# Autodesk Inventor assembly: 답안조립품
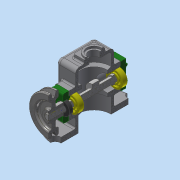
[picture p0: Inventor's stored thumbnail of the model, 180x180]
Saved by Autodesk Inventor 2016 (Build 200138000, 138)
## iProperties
Created: 2018-07
Part Number: 답안조립품
Material: 일반
Document SubType Name: Assembly
Designer: 2-PC02
Author: 2-PC02
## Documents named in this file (9)
- C:\Users\2-PC02\Desktop\480708V1008\480708V1008\답안조립품.iam
- C:\Users\2-PC02\Desktop\480708V1008\480708V1008\본체.ipt
- C:\Users\2-PC02\Desktop\480708V1008\뒤커버.ipt
- C:\Users\2-PC02\Desktop\480708V1008\편심축.ipt
- C:\Users\2-PC02\Desktop\480708V1008\베어링 12x32x10.ipt
- C:\Users\2-PC02\Desktop\480708V1008\앞커버.ipt
- C:\Users\2-PC02\Desktop\480708V1008\오일 실 12 25 7.ipt
- C:\Users\2-PC02\Desktop\480708V1008\V벨트풀리.ipt
- C:\Users\2-PC02\Desktop\480708V1008\키 4x4x10.ipt
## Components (1 placed, 1 different names)
1. V벨트풀리:1
